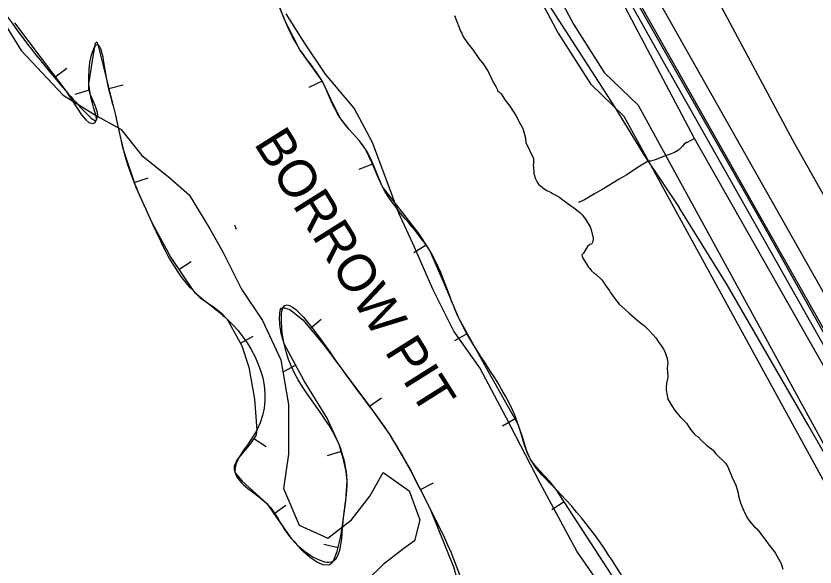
# Model space of a CAD drawing. Extents: x 3177185 to 3215018, y 812988 to 838321.
# Drawn here: x 3193125 to 3194486, y 821191 to 822130 of the extents above; entities that cross this region are included whole.
import ezdxf

# ---------------------------------------------------------------- set-up
doc = ezdxf.new("R2010")
doc.units = 0
for name, color, linetype in [('V-BORW-IDEN', 7, 'Continuous'), ('V-BORW-LINE', 7, 'Continuous'), ('V-LEVE-TOET', 7, 'Continuous'), ('V-RAIL-TRAK', 7, 'Continuous'), ('V-ROAD-CNTR', 7, 'Continuous'), ('V-SITE-VEGE', 7, 'Continuous'), ('V-SURV-LINE', 7, 'Continuous'), ('V-TOPO-SHOR', 7, 'Continuous')]:
    doc.layers.add(name, color=color, linetype=linetype)

msp = doc.modelspace()

# ---------------------------------------------------------------- linework, layer by layer
at = {"layer": 'V-BORW-LINE'}
for p, q in [((3193192.3, 822026.3), (3193212.3, 822041.3)), ((3193283.6, 822006.6), (3193307.8, 822012.5)), ((3193646.9, 822019), (3193624.4, 822008)), ((3193249.9, 822003.3), (3193225.9, 821996.4)), ((3193732.9, 821877.7), (3193709.7, 821868.4)), ((3193327, 821845.9), (3193350.6, 821854)), ((3193824.3, 821739.5), (3193803.2, 821726.1)), ((3193402.8, 821697.9), (3193423.6, 821711.8)), ((3193626.4, 821597.2), (3193645.5, 821613.3)), ((3193894.4, 821588.6), (3193872.5, 821576.4)), ((3193507.8, 821572.1), (3193529.7, 821584.1)), ((3193602, 821534.6), (3193580, 821522.7)), ((3193727.5, 821464.9), (3193748, 821479.3)), ((3193975.7, 821443.2), (3193953.9, 821431)), ((3193530.8, 821410.1), (3193551.6, 821396.2)), ((3193679.4, 821387.6), (3193655.6, 821380.1)), ((3193814.2, 821322.9), (3193836.5, 821334.1)), ((3194059.2, 821301.9), (3194038.3, 821288.3)), ((3193564.7, 821281.6), (3193585.1, 821296.1)), ((3193674.1, 821223.4), (3193649.8, 821229.3))]:
    msp.add_line(p, q, dxfattribs=at)
for points in [[(3193994.9, 821389.7), (3193988.5, 821412.6), (3193980.5, 821434.8), (3193930, 821524.7), (3193879.7, 821614.9), (3193855.2, 821672.7), (3193830.2, 821730.3), (3193812.1, 821758.6), (3193750, 821838.8), (3193742.1, 821854.5), (3193732.2, 821879.3), (3193720.8, 821903.1), (3193710.5, 821917.1), (3193692.9, 821936.5), (3193676.9, 821957.1), (3193661.9, 821988.2), (3193646.8, 822019.2), (3193628.1, 822045.9), (3193609.2, 822072.6), (3193585.9, 822117.5), (3193556.8, 822188.5)], [(3193123.1, 822118.2), (3193210.3, 822002.4), (3193237.2, 821961.6), (3193244.3, 821953), (3193249.4, 821948.6), (3193256.4, 821946.6), (3193259.5, 821948.1), (3193262.2, 821951.7), (3193264.6, 821959), (3193264.3, 821965.6), (3193260.4, 821977.5), (3193252.1, 821995.7), (3193249.5, 822004.9), (3193249.6, 822013.9), (3193257.2, 822064.6), (3193261.1, 822083.6), (3193263.1, 822086), (3193265.1, 822081.6), (3193272.4, 822051.9), (3193279.7, 822022.1), (3193287, 821992.6), (3193294.3, 821963), (3193301.3, 821931.8), (3193308.4, 821900.5), (3193329.6, 821838.3), (3193356.9, 821777.8), (3193389.1, 821718.5), (3193426.4, 821662.5), (3193439.5, 821649.1), (3193463.4, 821633.2), (3193475.1, 821624.3), (3193485.3, 821613.1), (3193510.2, 821567.7), (3193522, 821531.6), (3193531.8, 821476.8), (3193535.6, 821424), (3193533.8, 821414.6), (3193522.8, 821398.2), (3193502.2, 821374), (3193496.8, 821362.4), (3193496.8, 821356.8), (3193499, 821351.2), (3193510.8, 821337), (3193552.5, 821298.8), (3193573.4, 821269.3), (3193594.8, 821238.9), (3193611.4, 821220.7), (3193626.9, 821207.1), (3193638.8, 821199.1), (3193647.3, 821195.2), (3193658.3, 821194.3), (3193662.6, 821196.6), (3193666, 821201.1), (3193672.7, 821217.3), (3193678.9, 821243.3), (3193683, 821270), (3193687.5, 821303.8), (3193689.4, 821337.7), (3193688.1, 821353.3), (3193683, 821376.4), (3193675.7, 821399.4), (3193655.5, 821444.6), (3193616.3, 821508.1), (3193582.1, 821571.4), (3193577.1, 821588.8), (3193574.7, 821604.3), (3193574.1, 821615.4), (3193575.5, 821628.3), (3193577.6, 821632)], [(3193577.6, 821632), (3193580.7, 821633.2), (3193591.8, 821629.7), (3193613.8, 821612.2), (3193649.3, 821570), (3193682.1, 821525.7), (3193722.9, 821471.4), (3193762, 821415.9), (3193798.6, 821354.1), (3193831.6, 821288.3), (3193870.9, 821190.9), (3193884.5, 821142.2)], [(3194483.4, 820494.4), (3194475.1, 820588.2), (3194464.1, 820634.7), (3194443.8, 820680.4), (3194418.9, 820714.1), (3194335.6, 820798.4), (3194315.8, 820824.6), (3194306.8, 820838.3), (3194299.8, 820853), (3194289.1, 820881.8), (3194278.3, 820910.6), (3194266.8, 820941.3), (3194255.4, 820971.9), (3194213.1, 821064.7), (3194045.6, 821322.9), (3194034.9, 821336.3), (3194017, 821355), (3194008.5, 821364.7), (3194001.3, 821375.3), (3193994.9, 821389.7)]]:
    msp.add_lwpolyline(points, dxfattribs=at)
msp.add_spline([(3193316.9, 822598.6), (3193335.2, 822540.6), (3193410.3, 822427.7), (3193431.9, 822364.3), (3193469.1, 822310), (3193521.5, 822255.9), (3193609.2, 822072.6), (3193646.8, 822019.2), (3193676.9, 821957.1), (3193720.8, 821903.1), (3193750, 821838.8), (3193830.2, 821730.3), (3193879.7, 821614.9), (3193980.5, 821434.8), (3194001.3, 821375.3), (3194045.6, 821322.9), (3194255.4, 820971.9), (3194278.3, 820910.6), (3194299.8, 820853), (3194335.6, 820798.4), (3194443.8, 820680.4), (3194483.4, 820494.4), (3194474.8, 820430), (3194362.4, 820338.7), (3194243.4, 820273.7), (3194115.5, 820232.8), (3193985.1, 820192.2), (3193871, 820096.9), (3193700.8, 819982), (3193642.2, 819950.8), (3193574.5, 819997.4), (3193482.7, 820109.4), (3193411.4, 820226.4), (3193461, 820288.3), (3193516, 820325.3), (3193569.4, 820370.5), (3193689.7, 820437.3), (3193809.3, 820477.2), (3193921.8, 820552.8), (3193973.7, 820602), (3193968.2, 820665.5), (3193943.7, 820740.3), (3193889.6, 820861.5), (3193818.7, 820974.4), (3193871.9, 821026.9), (3193893.2, 821093.5), (3193831.6, 821288.3), (3193762, 821415.9), (3193682.1, 821525.7), (3193580.7, 821633.2), (3193582.1, 821571.4), (3193675.7, 821399.4), (3193689.4, 821337.7), (3193683, 821270), (3193666, 821201.1), (3193594.8, 821238.9), (3193552.5, 821298.8), (3193499, 821351.2), (3193535.6, 821424), (3193485.3, 821613.1), (3193426.4, 821662.5), (3193356.9, 821777.8), (3193308.4, 821900.5), (3193294.3, 821963), (3193279.7, 822022.1), (3193265.1, 822081.6), (3193249.6, 822013.9), (3193262.2, 821951.7), (3193210.3, 822002.4), (3193038.4, 822236.4), (3192901.1, 822477.4), (3192892.6, 822538.2), (3192940.3, 822603.2), (3192988.9, 822662), (3193107.6, 822723.1), (3193158.6, 822772.1), (3193217.2, 822790.6), (3193249.5, 822765), (3193290.2, 822685.8), (3193316.9, 822598.6)], degree=3, dxfattribs=at)
at = {"layer": 'V-LEVE-TOET'}
for points in [[(3193894.5, 822971.4), (3194028.2, 822704.5), (3194448.5, 821917.6)], [(3193715.3, 822746.3), (3193717.9, 822741.8), (3193794.1, 822610.8), (3193858.9, 822476), (3193911.1, 822371.7), (3194022.5, 822165.9), (3194144.7, 821975), (3194195.9, 821891.8), (3194255.3, 821803.4)], [(3194448.5, 821917.6), (3194600, 821648.8), (3194730.3, 821412.1), (3194889.3, 821132.9), (3195058.8, 820825.9), (3195075.3, 820785.1), (3195080.3, 820773.1), (3195087.5, 820766.1), (3195094.5, 820766.2), (3195101.6, 820771.9), (3195107.6, 820782.7), (3195113.8, 820796.7), (3195176.6, 820853), (3195190.5, 820860.2), (3195219.9, 820873.4), (3195237.6, 820893.1), (3195245.9, 820920.5), (3195264, 820997.9), (3195322.1, 821260.9), (3195389.9, 821526.1)], [(3195369.9, 819862.9), (3195294.5, 819981.2), (3195273.4, 820017.6), (3195233.7, 820077.8), (3195218.6, 820104.8), (3195199.4, 820136.6), (3195173.6, 820178.4), (3195142.1, 820229.4), (3195073.8, 820350.4), (3195014.1, 820460), (3194933, 820615.4), (3194826.9, 820807.9), (3194726, 820985.8), (3194603, 821208.6), (3194474, 821433.9), (3194336.7, 821672), (3194255.3, 821803.4)]]:
    msp.add_lwpolyline(points, dxfattribs=at)
at = {"layer": 'V-RAIL-TRAK'}
for points in [[(3194238.4, 822033.7), (3194009.1, 822443.2), (3193835.4, 822751.2), (3193727.3, 822943)], [(3194238.4, 822033.7), (3194389.3, 821767.4), (3194710.7, 821197.3), (3195003.1, 820677), (3195353.4, 820056.4), (3195586, 819645), (3195933.8, 819028.7), (3196235.6, 818491.2), (3196308.1, 818364.4)]]:
    msp.add_lwpolyline(points, dxfattribs=at)
at = {"layer": 'V-ROAD-CNTR'}
for points in [[(3193546.7, 823116.4), (3193719.6, 822803.7), (3193783.2, 822690.8), (3193839.5, 822561.1), (3193931.2, 822385.2), (3194075.1, 822116.1), (3194127.2, 822033.7), (3194185.2, 821977.8), (3194639.7, 821147.1), (3195029.5, 820446.4), (3195072.9, 820348.7), (3195192.1, 820158.7), (3195238.4, 820041.1), (3195343.7, 819857.8), (3195584.5, 819427.5), (3195690.6, 819249.8), (3195813.3, 819032.3), (3196001.4, 818698.6), (3196174.6, 818374.5)], [(3193520.4, 823101.8), (3193693.4, 822789.1), (3193756.3, 822677.4), (3193812.4, 822548.2), (3193904.7, 822371.2), (3194049.2, 822101), (3194103.8, 822014.6), (3194161.1, 821959.4), (3194613.5, 821132.6), (3195002.6, 820433), (3195046.3, 820334.6), (3195165.2, 820145.1), (3195211.3, 820028), (3195317.6, 819843), (3195558.5, 819412.5), (3195664.6, 819234.7), (3195787.2, 819017.6), (3195975.1, 818684.1), (3196148.1, 818360.4)], [(3193654.2, 823085.5), (3194393.6, 821781.9), (3194932.5, 820818.5), (3195643.8, 819559.4), (3196039.6, 818863.6), (3196103.7, 818747.1), (3196200.1, 818577.4), (3196283.3, 818430.9), (3196319.7, 818367.1)]]:
    msp.add_lwpolyline(points, dxfattribs=at)
at = {"layer": 'V-SITE-VEGE'}
for p, q in [((3193616.7, 822084.4), (3193585.4, 822133.5)), ((3193098.7, 822129), (3193134.4, 822071)), ((3193872.3, 822131.1), (3193880.6, 822110.4)), ((3193880.6, 822110.4), (3193882.8, 822104.1)), ((3193882.8, 822104.1), (3193885.1, 822100.9)), ((3193885.1, 822100.9), (3193887.4, 822094.5)), ((3193887.4, 822094.5), (3193896.6, 822080.9)), ((3193652.4, 822030.7), (3193616.7, 822084.4)), ((3193896.6, 822080.9), (3193902.8, 822073.7)), ((3193134.4, 822071), (3193205.9, 821995)), ((3193902.8, 822073.7), (3193913.6, 822057.8)), ((3193913.6, 822057.8), (3193921.3, 822048.2)), ((3193921.3, 822048.2), (3193929.7, 822035.4)), ((3193701.5, 821972.7), (3193652.4, 822030.7)), ((3193929.7, 822035.4), (3193938.8, 822016.3)), ((3193938.8, 822016.3), (3193942.7, 822009.9)), ((3193942.7, 822009.9), (3193945.7, 822004.3)), ((3193945.7, 822004.3), (3193945.7, 822002)), ((3193945.7, 822002), (3193948.8, 822000.3)), ((3193948.8, 822000.3), (3193951.9, 821997.1)), ((3193951.9, 821997.1), (3193958.8, 821986.8)), ((3193205.9, 821995), (3193263.9, 821959.3)), ((3193958.8, 821986.8), (3193966.5, 821976.4)), ((3193732.8, 821914.6), (3193701.5, 821972.7)), ((3193966.5, 821976.4), (3193972.7, 821966.8)), ((3193263.9, 821959.3), (3193304.1, 821936.9)), ((3193972.7, 821966.8), (3193978, 821958.8)), ((3193978, 821958.8), (3193981.1, 821952.5)), ((3193981.1, 821952.5), (3193988.7, 821938.1)), ((3193304.1, 821936.9), (3193339.8, 821892.2)), ((3193988.7, 821938.1), (3193990.9, 821930.2)), ((3193990.9, 821930.2), (3193993.1, 821921.5)), ((3193777.4, 821794), (3193732.8, 821914.6)), ((3193993.1, 821921.5), (3193993.8, 821914.4)), ((3193993.8, 821914.4), (3194006.7, 821887.3)), ((3193339.8, 821892.2), (3193384.5, 821856.5)), ((3194006.7, 821887.3), (3194006.8, 821879.2)), ((3194006.8, 821879.2), (3194006.4, 821875.2)), ((3194006.4, 821875.2), (3194006.9, 821873.2)), ((3194006.9, 821873.2), (3194007.4, 821861.5)), ((3194007.4, 821861.5), (3194010.3, 821852.6)), ((3193384.5, 821856.5), (3193420.2, 821825.2)), ((3194010.3, 821852.6), (3194013.2, 821847)), ((3194013.2, 821847), (3194015.6, 821843.3)), ((3194015.6, 821843.3), (3194019.3, 821839.7)), ((3194019.3, 821839.7), (3194025, 821835.3)), ((3194025, 821835.3), (3194029.5, 821832.6)), ((3194029.5, 821832.6), (3194036.8, 821829)), ((3193420.2, 821825.2), (3193455.9, 821767.1)), ((3194036.8, 821829), (3194039.6, 821827.4)), ((3194039.6, 821827.4), (3194042.5, 821825.8)), ((3194042.5, 821825.8), (3194051.4, 821821)), ((3194051.4, 821821), (3194055.5, 821817.8)), ((3194055.5, 821817.8), (3194059.1, 821815)), ((3194059.1, 821815), (3194065.7, 821810.3)), ((3194065.7, 821810.3), (3194069.7, 821806.7)), ((3194069.7, 821806.7), (3194075, 821803.5)), ((3193804.2, 821735.9), (3193777.4, 821794)), ((3194075, 821803.5), (3194085.6, 821795.1)), ((3194085.6, 821795.1), (3194089.7, 821791.1)), ((3194089.7, 821791.1), (3194095.4, 821783.9)), ((3194095.4, 821783.9), (3194103.6, 821770.6)), ((3193455.9, 821767.1), (3193478.2, 821726.9)), ((3194103.6, 821770.6), (3194104.5, 821767.8)), ((3194104.5, 821767.8), (3194108.7, 821751.2)), ((3194108.7, 821751.2), (3194108.3, 821745.6)), ((3194098.7, 821737), (3194092.3, 821726)), ((3194103.1, 821740.3), (3194098.7, 821737)), ((3194105.5, 821741.1), (3194103.1, 821740.3)), ((3194107.1, 821743.5), (3194105.5, 821741.1)), ((3194108.3, 821745.6), (3194107.1, 821743.5)), ((3193478.2, 821726.9), (3193509.5, 821664.4)), ((3193835.4, 821664.4), (3193804.2, 821735.9)), ((3194092.3, 821726), (3194089.5, 821722.8)), ((3194089.5, 821722.8), (3194090, 821720.7)), ((3194090, 821720.7), (3194091.2, 821717.1)), ((3194091.2, 821717.1), (3194097.4, 821707.5)), ((3194097.4, 821707.5), (3194100.6, 821701.8)), ((3194100.6, 821701.8), (3194103.1, 821699.4)), ((3194103.1, 821699.4), (3194106, 821695.8)), ((3194106, 821695.8), (3194110.9, 821691)), ((3194110.9, 821691), (3194112.9, 821689.8)), ((3194112.9, 821689.8), (3194123.1, 821680.2)), ((3194123.1, 821680.2), (3194126, 821676.2)), ((3194126, 821676.2), (3194129.2, 821671.8)), ((3194129.2, 821671.8), (3194133.7, 821665.4)), ((3193509.5, 821664.4), (3193545.2, 821610.8)), ((3193871.2, 821592.9), (3193835.4, 821664.4)), ((3194133.7, 821665.4), (3194136.2, 821661.8)), ((3194136.2, 821661.8), (3194137.4, 821659.3)), ((3194137.4, 821659.3), (3194144.8, 821648.9)), ((3194144.8, 821648.9), (3194153, 821638.9)), ((3194153, 821638.9), (3194163.6, 821629.3)), ((3194163.6, 821629.3), (3194169.7, 821623.3)), ((3194169.7, 821623.3), (3194187.2, 821608.5)), ((3193545.2, 821610.8), (3193576.5, 821543.8)), ((3194187.2, 821608.5), (3194196.2, 821601.7)), ((3194196.2, 821601.7), (3194201.9, 821596.1)), ((3193915.8, 821530.4), (3193871.2, 821592.9)), ((3194201.9, 821596.1), (3194210.5, 821587.3)), ((3194210.5, 821587.3), (3194215.4, 821581.2)), ((3194215.4, 821581.2), (3194220.7, 821573.6)), ((3194220.7, 821573.6), (3194224, 821568.8)), ((3194224, 821568.8), (3194227.7, 821563.2)), ((3194227.7, 821563.2), (3194230.6, 821557.9)), ((3194230.6, 821557.9), (3194234.7, 821545.9)), ((3193576.5, 821543.8), (3193589.9, 821467.8)), ((3194234.7, 821545.9), (3194235.6, 821539)), ((3194235.6, 821539), (3194234.9, 821529.7)), ((3193960.5, 821445.5), (3193915.8, 821530.4)), ((3194234.9, 821529.7), (3194235.3, 821523.6)), ((3194235.3, 821523.6), (3194235.8, 821514.7)), ((3194235.4, 821511.5), (3194233.5, 821503.4)), ((3194235.8, 821514.7), (3194235.4, 821511.5)), ((3194233.5, 821503.4), (3194232.8, 821496.5)), ((3194232.8, 821496.5), (3194232.8, 821492.1)), ((3194232.8, 821492.1), (3194234.5, 821483.2)), ((3194234.5, 821483.2), (3194235.8, 821477.1)), ((3193589.9, 821467.8), (3193589.9, 821382.9)), ((3194235.8, 821477.1), (3194242.4, 821465.5)), ((3194242.4, 821465.5), (3194247.7, 821457.4)), ((3194247.7, 821457.4), (3194251, 821453.4)), ((3194251, 821453.4), (3194256.7, 821446.6)), ((3194018.5, 821333.8), (3193960.5, 821445.5)), ((3194256.7, 821446.6), (3194260.3, 821443.4)), ((3194260.3, 821443.4), (3194267.3, 821436.2)), ((3194267.3, 821436.2), (3194273.4, 821426.6)), ((3194273.4, 821426.6), (3194280.8, 821417.7)), ((3194280.8, 821417.7), (3194283.7, 821414.9)), ((3194283.7, 821414.9), (3194287.3, 821412.5)), ((3194287.3, 821412.5), (3194293.4, 821406.5)), ((3194293.4, 821406.5), (3194302.4, 821398.1)), ((3194302.4, 821398.1), (3194310.1, 821392.1)), ((3193589.9, 821382.9), (3193580.9, 821324.8)), ((3194310.1, 821392.1), (3194313.4, 821389.3)), ((3194313.4, 821389.3), (3194317.1, 821384.5)), ((3194317.1, 821384.5), (3194334.2, 821367.7)), ((3194334.2, 821367.7), (3194337.9, 821361.3)), ((3194337.9, 821361.3), (3194344.1, 821346)), ((3193728.3, 821311.4), (3193750.6, 821351.7)), ((3193750.6, 821351.7), (3193764, 821342.7)), ((3193764, 821342.7), (3193795.3, 821320.4)), ((3194344.1, 821346), (3194345.4, 821343.2)), ((3194345.4, 821343.2), (3194351.6, 821330.3)), ((3194081, 821217.6), (3194018.5, 821333.8)), ((3194351.6, 821330.3), (3194355.3, 821317.4)), ((3193580.9, 821324.8), (3193607.7, 821262.3)), ((3193795.3, 821320.4), (3193813.1, 821271.2)), ((3194355.3, 821317.4), (3194356.2, 821312.1)), ((3193697, 821271.2), (3193728.3, 821311.4)), ((3194356.2, 821312.1), (3194357.9, 821305.7)), ((3194357.9, 821305.7), (3194359.5, 821300)), ((3194359.5, 821300), (3194361.6, 821294.4)), ((3194361.6, 821294.4), (3194367, 821282.3)), ((3194367, 821282.3), (3194371.5, 821273.9)), ((3194371.5, 821273.9), (3194375.2, 821268.6)), ((3193607.7, 821262.3), (3193656.8, 821240)), ((3193656.8, 821240), (3193697, 821271.2)), ((3193813.1, 821271.2), (3193804.2, 821235.5)), ((3194375.2, 821268.6), (3194382.5, 821260.2)), ((3194382.5, 821260.2), (3194386.6, 821256.2)), ((3194386.6, 821256.2), (3194390.3, 821252.2)), ((3194390.3, 821252.2), (3194397.7, 821243)), ((3193804.2, 821235.5), (3193786.3, 821222.1)), ((3194397.7, 821243), (3194402.6, 821235.8)), ((3194402.6, 821235.8), (3194406.7, 821230.5)), ((3193786.3, 821222.1), (3193750.6, 821195.3)), ((3194406.7, 821230.5), (3194410.8, 821224.9)), ((3194410.8, 821224.9), (3194417.3, 821216.5)), ((3194161.4, 821101.5), (3194081, 821217.6)), ((3194417.3, 821216.5), (3194419.4, 821213.7)), ((3194419.4, 821213.7), (3194428, 821198)), ((3193750.6, 821195.3), (3193723.8, 821168.5)), ((3194428, 821198), (3194431.8, 821187.1))]:
    msp.add_line(p, q, dxfattribs=at)
at = {"layer": 'V-SURV-LINE'}
for points in [[(3194010.9, 822526.1), (3195297.4, 820248.2)], [(3195271.3, 820233.4), (3193984.8, 822511.3)]]:
    msp.add_lwpolyline(points, dxfattribs=at)
at = {"layer": 'V-TOPO-SHOR'}
for points in [[(3195564, 819660.7), (3195052.1, 820581.1), (3194839.3, 820937.7), (3194281, 821921.4), (3194057, 822347), (3193780.9, 822818.6), (3193257.4, 823744.7), (3192803, 824538.5), (3192509.7, 825084.9), (3192365.9, 825332.3), (3191974.7, 826039.8)], [(3194281, 821921.4), (3194274.8, 821917.7), (3194268.7, 821914.6), (3194267.6, 821914.1), (3194263.5, 821911.4), (3194260.5, 821908), (3194259.9, 821906.9), (3194254, 821901.5), (3194247.3, 821897.4), (3194241.4, 821895.1), (3194228.2, 821890.5), (3194221.4, 821887.9), (3194214, 821884.6), (3194206.2, 821882.8), (3194202.3, 821882.5), (3194185.3, 821872.1), (3194181.5, 821869.6), (3194164.9, 821858.8), (3194152.8, 821852.1), (3194125.3, 821834.9), (3194110.8, 821827), (3194102.1, 821821.6), (3194094, 821816.5), (3194085, 821812.7), (3194083.2, 821812.1)], [(3193497.5, 821774.3), (3193499.4, 821769.5), (3193500.7, 821766.8)]]:
    msp.add_lwpolyline(points, dxfattribs=at)

# ---------------------------------------------------------------- texts
at = {"layer": 'V-BORW-IDEN'}
msp.add_text('BORROW PIT', height=64, rotation=302.1496, dxfattribs=at).set_placement((3193529.6, 821912.7))

doc.saveas('drawing.dxf')
